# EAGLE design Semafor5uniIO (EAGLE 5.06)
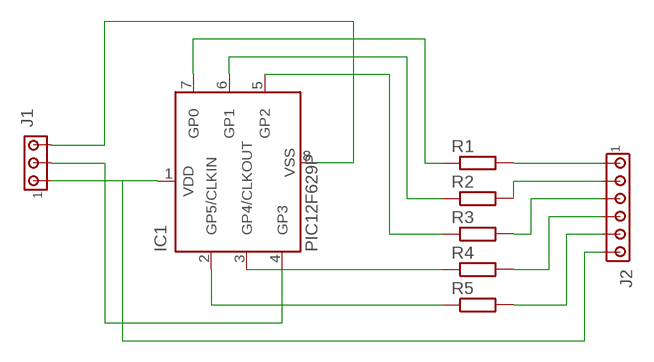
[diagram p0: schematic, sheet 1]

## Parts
IC1  PIC12F629P  [DIL8]
J1  MTA03-100  [10X03MTA]
J2  MTA06-100  [10X06MTA]
R1  R-EU_0207/10  [0207/10]
R2  R-EU_0207/10  [0207/10]
R3  R-EU_0207/10  [0207/10]
R4  R-EU_0207/10  [0207/10]
R5  R-EU_0207/10  [0207/10]

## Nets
N$1: J2.6 R1.2
N$2: J2.5 R2.2
N$3: J2.4 R3.2
N$4: J2.3 R4.2
N$5: J2.2 R5.2
N$6: IC1.1(VDD) J1.1 J2.1
N$7: IC1.4(GP3) J1.2
N$8: IC1.8(VSS) J1.3
N$9: IC1.5(GP2) R3.1
N$10: IC1.6(GP1) R2.1
N$11: IC1.7(GP0) R1.1
N$12: IC1.3(GP4/CLKOUT) R4.1
N$13: IC1.2(GP5/CLKIN) R5.1

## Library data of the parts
IC1 = microchip:PIC12F6*: Data Sheet 8-Pin FLASH-Based 8-Bit CMOS Microcontrollers Source: http://www.microchip.com .. 41190c.pdf
J1 = con-amp:MTA03-100: AMP connector
J2 = con-amp:MTA06-100: AMP connector
R1-R5 = resistor:R-EU_: RESISTOR, European symbol

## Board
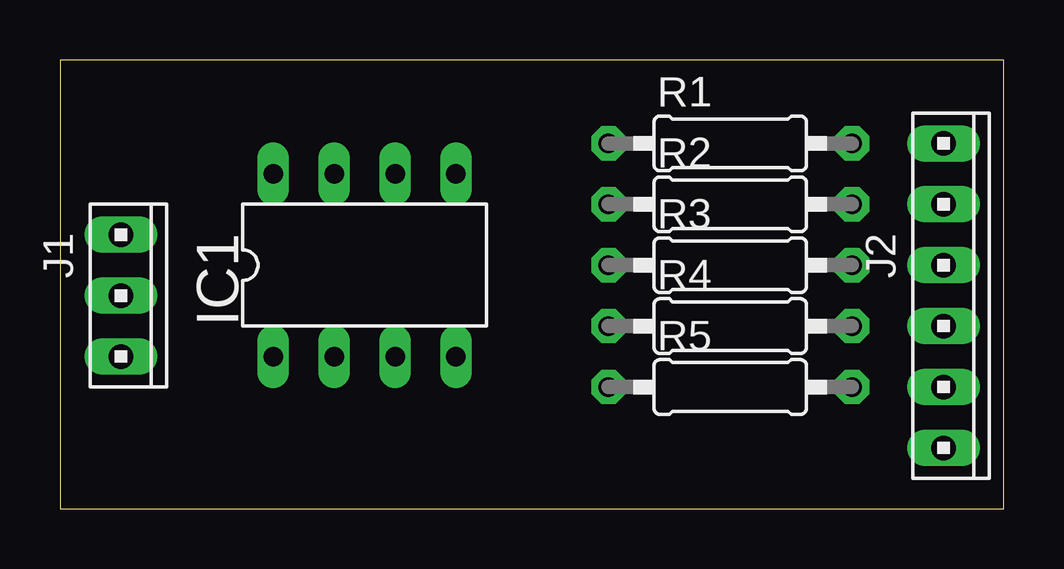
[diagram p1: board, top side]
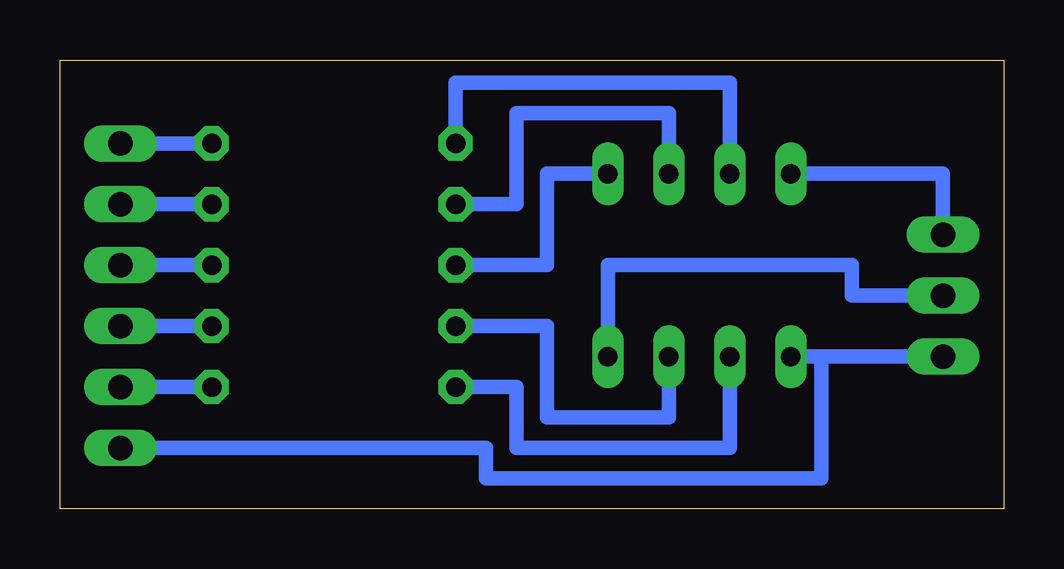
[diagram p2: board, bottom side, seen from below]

Size 39.35 x 18.72 mm. Coordinates in mm from the lower left corner, seen from the top.
Outline: 0,0 39.35,0 39.35,18.72 0,18.72 0,0
Copper layers (1*16): Top 0.035mm / dielectric 1.5mm / Bottom 0.035mm
Design rules "default": minimum track width 10mil, minimum drill 24mil, track to track 8mil, track to pad 8mil, pad to pad 8mil, via to via 8mil, smd to smd 8mil, copper to edge 40mil, drill to drill 8mil, minimum pad ring 10mil, minimum via ring 8mil, stop-mask expansion 4mil, vias tented up to drill 0mil, thermal gap 10mil

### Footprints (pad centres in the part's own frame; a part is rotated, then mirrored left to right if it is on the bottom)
DIL8 = drill 0.813 long: 1 -3.81,-3.81; 2 -1.27,-3.81; 3 1.27,-3.81; 4 3.81,-3.81; 5 3.81,3.81; 6 1.27,3.81; 7 -1.27,3.81; 8 -3.81,3.81
10X03MTA = drill 1.016 long: 1 2.54,0; 2 0,0; 3 -2.54,0
10X06MTA = drill 1.016 long: 1 6.35,0; 2 3.81,0; 3 1.27,0; 4 -1.27,0; 5 -3.81,0; 6 -6.35,0
0207/10 = drill 0.813 octagon: 1 -5.08,0; 2 5.08,0

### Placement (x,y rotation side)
IC1  12.7,10.16 0 top
J1  2.54,8.89 270 top
J2  36.83,8.89 270 top
R1  27.94,15.24 0 top
R2  27.94,12.7 0 top
R3  27.94,10.16 0 top
R4  27.94,7.62 0 top
R5  27.94,5.08 0 top

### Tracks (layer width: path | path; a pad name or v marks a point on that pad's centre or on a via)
N$1
  Bottom 0.61: R1.2 J2.6
N$2
  Bottom 0.61: R2.2 J2.5
N$3
  Bottom 0.61: R3.2 J2.4
N$4
  Bottom 0.61: R4.2 J2.3
N$5
  Bottom 0.61: R5.2 J2.2
N$6
  Bottom 0.61: 7.62,6.35 IC1.1 | J1.1 7.62,6.35 | J2.1 21.59,2.54 21.59,1.27 7.62,1.27 7.62,6.35
N$7
  Bottom 0.61: IC1.4 16.51,10.16 6.35,10.16 6.35,8.89 J1.2
N$8
  Bottom 0.61: IC1.8 2.54,13.97 J1.3
N$9
  Bottom 0.61: IC1.5 19.05,13.97 19.05,10.16 R3.1
N$10
  Bottom 0.61: IC1.6 13.97,16.51 20.32,16.51 20.32,12.7 R2.1
N$11
  Bottom 0.61: IC1.7 11.43,17.78 22.86,17.78 R1.1
N$12
  Bottom 0.61: IC1.3 13.97,3.81 19.05,3.81 19.05,7.62 R4.1
N$13
  Bottom 0.61: R5.1 20.32,5.08 20.32,2.54 11.43,2.54 IC1.2
S$1  (via drill 0.5 pad 1.27, 0.5 pad 1.42)
  other vias: 33.02,12.7 33.02,12.7 33.02,15.24 33.02,10.16 33.02,7.62 33.02,5.08 22.86,5.08 22.86,7.62 22.86,10.16 22.86,12.7 22.86,15.24 33.02,15.24 2.54,11.43 8.89,13.97 11.43,13.97 13.97,13.97 16.51,13.97 8.89,6.35 11.43,6.35 13.97,6.35 16.51,6.35 36.83,15.24 36.83,12.7 36.83,10.16 36.83,7.62 36.83,5.08 36.83,2.54 2.54,11.43 2.54,8.89 2.54,6.35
